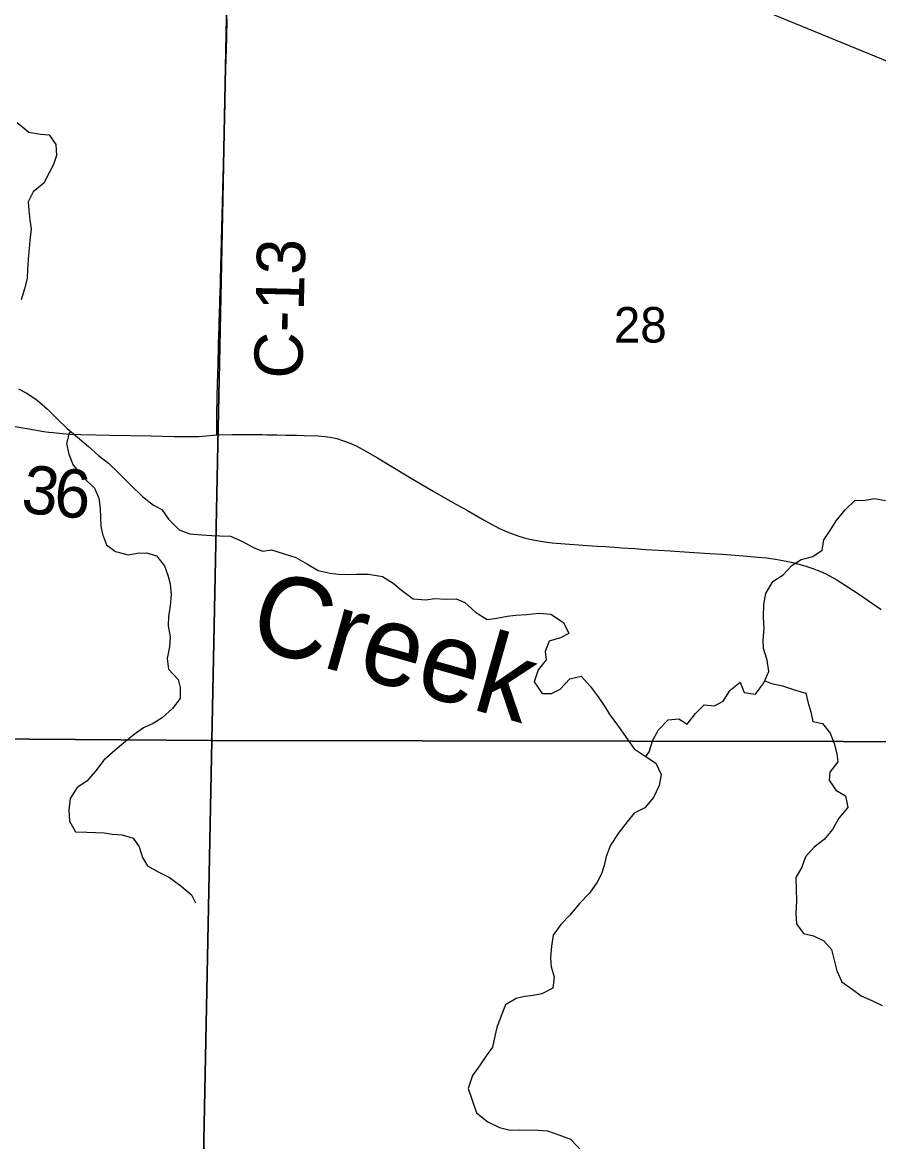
# Model space of a CAD drawing. Extents: x 0 to 34, y 0 to 22.
# Drawn here: x 4.621 to 5.125, y 15.009 to 15.668 of the extents above; entities that cross this region are included whole.
import ezdxf

# ---------------------------------------------------------------- set-up
doc = ezdxf.new("R2010")
doc.units = 0
for name, color, linetype in [('GM_X_Corporation', 7, 'Continuous'), ('GM_X_County_Road', 7, 'Continuous'), ('GM_X_County_Road_Text', 7, 'Continuous'), ('GM_X_Minor_River', 7, 'Continuous'), ('GM_X_Minor_River_Text', 7, 'Continuous'), ('GM_X_Rail_Line', 7, 'Continuous'), ('GM_X_Section_Text', 7, 'Continuous')]:
    doc.layers.add(name, color=color, linetype=linetype)

msp = doc.modelspace()

# ---------------------------------------------------------------- linework, layer by layer
at = {"layer": 'GM_X_Corporation'}
for points in [[(4.74242, 15.74864), (4.73217, 15.24548), (4.22309, 15.24934), (4.22989, 15.74816)], [(5.23921, 15.74697), (5.2282, 15.24475), (4.73217, 15.24548), (4.74242, 15.74864)], [(4.22309, 15.24934), (4.73217, 15.24548), (4.72231, 14.74459), (4.71681, 14.74463), (4.22002, 14.74366), (4.21755, 14.74349)], [(5.2282, 15.24475), (5.21872, 14.74348), (4.72231, 14.74459), (4.73217, 15.24548)]]:
    msp.add_lwpolyline(points, close=True, dxfattribs=at)
at = {"layer": 'GM_X_County_Road'}
for points in [[(4.73516, 15.42552), (4.73514, 15.4363), (4.73526, 15.43986), (4.73539, 15.44526), (4.73539, 15.44743), (4.73544, 15.45085), (4.73549, 15.45302), (4.73555, 15.45551), (4.73591, 15.46762), (4.73616, 15.47663), (4.73621, 15.47911), (4.73651, 15.48905), (4.73665, 15.49308), (4.73675, 15.49618), (4.73723, 15.51109), (4.73729, 15.51264), (4.73736, 15.51512), (4.73743, 15.5173), (4.73779, 15.53221), (4.73814, 15.54774), (4.73852, 15.56232), (4.7387, 15.57039), (4.73913, 15.58436), (4.73975, 15.60611), (4.74006, 15.62042), (4.74017, 15.62787), (4.74038, 15.63563), (4.74085, 15.65241), (4.741, 15.65924), (4.74128, 15.67037)], [(4.59378, 15.43804), (4.59465, 15.43756), (4.59798, 15.436), (4.60205, 15.43423), (4.60554, 15.43304), (4.60892, 15.43209), (4.61414, 15.4309), (4.62442, 15.42905), (4.63334, 15.42758), (4.63618, 15.42716), (4.6389, 15.42684), (4.64424, 15.42634), (4.64889, 15.42602), (4.65505, 15.42573), (4.6722, 15.4254), (4.69659, 15.42492), (4.71003, 15.42459), (4.71673, 15.42447), (4.72163, 15.42451), (4.72455, 15.42464), (4.72685, 15.4248), (4.73516, 15.42552)], [(4.73516, 15.42552), (4.74425, 15.42569), (4.74767, 15.42571), (4.75667, 15.42569), (4.76101, 15.42565), (4.76194, 15.42563), (4.76471, 15.42558), (4.77059, 15.42552), (4.77575, 15.42535), (4.78216, 15.42525), (4.78665, 15.42514), (4.79509, 15.42487), (4.79887, 15.42459), (4.80199, 15.42416), (4.80588, 15.42328), (4.80928, 15.42229), (4.81317, 15.42082), (4.81722, 15.41896), (4.82124, 15.41684), (4.82977, 15.41189), (4.83892, 15.40647), (4.84829, 15.40078), (4.86269, 15.39234), (4.87425, 15.38572), (4.88275, 15.38101), (4.89255, 15.37537), (4.89836, 15.3722), (4.90214, 15.37023), (4.90614, 15.36847), (4.90937, 15.36716), (4.9131, 15.36585), (4.91698, 15.36475), (4.91951, 15.36415), (4.92241, 15.36356), (4.92476, 15.36306), (4.92727, 15.36265), (4.92953, 15.36234), (4.93271, 15.36202), (4.94284, 15.3612), (4.95341, 15.36043), (4.95941, 15.36001), (4.96406, 15.35968), (4.97181, 15.35919), (4.97367, 15.35907), (4.98142, 15.35852), (4.98762, 15.35809), (4.99537, 15.35755), (5.00219, 15.35715), (5.01329, 15.35645), (5.02545, 15.35565), (5.0332, 15.35516), (5.04517, 15.35432), (5.05396, 15.35358), (5.05891, 15.35302), (5.06415, 15.35228), (5.06845, 15.35153), (5.07334, 15.35052), (5.07789, 15.34944), (5.08006, 15.34885), (5.0821, 15.34826), (5.08624, 15.34685), (5.0903, 15.34523), (5.09342, 15.34381), (5.09649, 15.34226), (5.10028, 15.3401), (5.10585, 15.33666), (5.11312, 15.33186), (5.12647, 15.32275)]]:
    msp.add_lwpolyline(points, dxfattribs=at)
at = {"layer": 'GM_X_Minor_River'}
for points in [[(4.61757, 15.60947), (4.62455, 15.60373), (4.63137, 15.60254), (4.63649, 15.60212), (4.64044, 15.59659), (4.64077, 15.59013), (4.63902, 15.58483), (4.63652, 15.57992), (4.63325, 15.57368), (4.62695, 15.56861), (4.62406, 15.56275), (4.62441, 15.55781), (4.62512, 15.55192), (4.62585, 15.5468), (4.62504, 15.53997), (4.62462, 15.53523), (4.62401, 15.52897), (4.62377, 15.52271), (4.62355, 15.51759), (4.62198, 15.51153), (4.62004, 15.50509)], [(4.61833, 15.45255), (4.62325, 15.45005), (4.62948, 15.44601), (4.63551, 15.44066), (4.64116, 15.43492), (4.647, 15.42919), (4.65323, 15.42421), (4.65964, 15.41865), (4.66548, 15.4133), (4.67133, 15.40889), (4.67736, 15.40315), (4.68452, 15.39589), (4.69149, 15.3892), (4.6979, 15.38402), (4.70282, 15.38152), (4.70676, 15.3758), (4.71297, 15.36968), (4.71922, 15.36717), (4.72642, 15.36654), (4.7323, 15.36631)], [(4.64901, 15.42758), (4.64831, 15.42652), (4.64675, 15.42046), (4.64803, 15.41419), (4.65064, 15.40772), (4.65666, 15.40046), (4.66306, 15.39415), (4.66568, 15.38825), (4.66658, 15.38217), (4.66673, 15.37686), (4.66688, 15.37173), (4.6678, 15.36698), (4.67022, 15.3607), (4.6755, 15.35687), (4.68289, 15.35492), (4.68821, 15.35582), (4.69371, 15.35597), (4.69958, 15.35422), (4.70447, 15.3483), (4.70633, 15.34279), (4.70762, 15.33784), (4.70833, 15.33158), (4.70771, 15.32475), (4.70672, 15.3185), (4.70649, 15.313), (4.70777, 15.30654), (4.70735, 15.30066), (4.70597, 15.29384), (4.70669, 15.28757), (4.71233, 15.28145), (4.71363, 15.2767), (4.71358, 15.27025), (4.70917, 15.2644), (4.70306, 15.25895), (4.69773, 15.25557), (4.69201, 15.25296), (4.68648, 15.24901), (4.68019, 15.24394), (4.67503, 15.23961), (4.66873, 15.23397), (4.66375, 15.22737), (4.65858, 15.22152), (4.65286, 15.21777), (4.64883, 15.21135), (4.64802, 15.20452), (4.64836, 15.19807), (4.65191, 15.19178), (4.65855, 15.19154), (4.6688, 15.19109), (4.67353, 15.19029), (4.67941, 15.18987), (4.68585, 15.18792), (4.68942, 15.18296), (4.69146, 15.17669), (4.69446, 15.17173), (4.70069, 15.16808), (4.70731, 15.1648), (4.71392, 15.16001), (4.72033, 15.15465), (4.72257, 15.14989)], [(4.98793, 15.23602), (4.98979, 15.23876), (4.99193, 15.24577), (4.99539, 15.25181), (5.00094, 15.25765), (5.0072, 15.25836), (5.01211, 15.2551), (5.01709, 15.26133), (5.02225, 15.2666), (5.02832, 15.26598), (5.03346, 15.2686), (5.03749, 15.27521), (5.04341, 15.27991), (5.04583, 15.27382), (5.05246, 15.27282), (5.05725, 15.27943), (5.06034, 15.28624), (5.05925, 15.29288), (5.05721, 15.29973), (5.05687, 15.30467), (5.05749, 15.31149), (5.05716, 15.31795), (5.0574, 15.32572), (5.05859, 15.33217), (5.06262, 15.33916), (5.06872, 15.3431), (5.07389, 15.34856), (5.07922, 15.35212), (5.08626, 15.35397), (5.0916, 15.35753), (5.09259, 15.36379), (5.09643, 15.36926), (5.09988, 15.37493), (5.10524, 15.38134), (5.11116, 15.38699), (5.11591, 15.38695), (5.12255, 15.38804), (5.129, 15.38685)], [(4.7323, 15.36631), (4.73705, 15.36608), (4.7433, 15.36585), (4.74992, 15.36295), (4.75673, 15.3591), (4.76202, 15.35698), (4.76734, 15.35789), (4.77435, 15.35556), (4.78173, 15.35322), (4.78853, 15.34938), (4.79496, 15.34572), (4.80196, 15.34415), (4.80689, 15.34355), (4.81239, 15.34332), (4.81752, 15.34347), (4.82454, 15.34341), (4.83269, 15.34202), (4.83911, 15.33818), (4.84401, 15.33397), (4.8508, 15.32899), (4.8582, 15.32836), (4.86352, 15.32908), (4.86997, 15.32884), (4.87623, 15.32898), (4.88134, 15.32686), (4.88756, 15.32112), (4.89436, 15.3167), (4.90005, 15.31761), (4.90613, 15.3187), (4.91107, 15.31924), (4.91753, 15.31976), (4.92493, 15.32046), (4.93195, 15.31984), (4.93931, 15.31504), (4.94249, 15.30856), (4.93754, 15.30594), (4.93088, 15.3041), (4.92856, 15.29785), (4.92909, 15.29311), (4.9245, 15.28707), (4.92217, 15.28007), (4.92686, 15.2732), (4.93236, 15.27316), (4.93732, 15.27578), (4.94305, 15.28181), (4.94971, 15.28346), (4.95498, 15.27754), (4.95967, 15.27124), (4.96305, 15.26629), (4.96699, 15.25999), (4.97131, 15.25427), (4.9762, 15.24721), (4.98089, 15.24054), (4.9875, 15.23631), (4.99373, 15.23209), (4.99691, 15.22543), (4.99572, 15.21898), (4.99244, 15.21199), (4.98728, 15.20595), (4.98099, 15.20278), (4.97678, 15.19769), (4.97161, 15.1907), (4.96701, 15.18391), (4.96449, 15.17729), (4.96331, 15.17198), (4.96176, 15.16706), (4.95926, 15.16215), (4.95466, 15.15554), (4.94873, 15.14951), (4.94299, 15.14273), (4.93783, 15.13707), (4.93323, 15.13085), (4.93223, 15.1244), (4.93161, 15.11777), (4.93214, 15.11226), (4.93381, 15.10637), (4.933, 15.09973), (4.92653, 15.09636), (4.92158, 15.09526), (4.91665, 15.09473), (4.91152, 15.09363), (4.90523, 15.08988), (4.90271, 15.08345), (4.90001, 15.07645), (4.89883, 15.07134), (4.89746, 15.0649), (4.89381, 15.0598), (4.89036, 15.05452), (4.88576, 15.04829), (4.88324, 15.04053), (4.88565, 15.03368), (4.88807, 15.02626), (4.89486, 15.0209), (4.90167, 15.01762), (4.90791, 15.01606), (4.91323, 15.01621), (4.92461, 15.01612), (4.92992, 15.0157), (4.93654, 15.01318), (4.94355, 15.01066), (4.95013, 15.00359)], [(5.05784, 15.28073), (5.06181, 15.27901), (5.06825, 15.27764), (5.07601, 15.27511), (5.08207, 15.27336), (5.08317, 15.26823), (5.08502, 15.26233), (5.08612, 15.25663), (5.0918, 15.25545), (5.09632, 15.24991), (5.09874, 15.24382), (5.1004, 15.23774), (5.10094, 15.23299), (5.09615, 15.22696), (5.09573, 15.22222), (5.09968, 15.21631), (5.10534, 15.21285), (5.10681, 15.206), (5.10145, 15.19978), (5.0978, 15.19317), (5.09282, 15.18714), (5.08691, 15.18263), (5.08193, 15.17697), (5.0798, 15.17092), (5.07615, 15.16487), (5.07629, 15.15785), (5.07662, 15.15102), (5.07619, 15.14362), (5.07652, 15.13755), (5.08066, 15.13182), (5.08653, 15.13045), (5.09258, 15.12756), (5.09709, 15.1224), (5.09876, 15.11613), (5.10023, 15.10986), (5.10322, 15.10338), (5.10926, 15.09897), (5.11473, 15.09514), (5.12097, 15.09243), (5.12702, 15.08954)]]:
    msp.add_lwpolyline(points, dxfattribs=at)
at = {"layer": 'GM_X_Rail_Line'}
msp.add_lwpolyline([(4.96716, 15.7129), (5.05909, 15.67461), (5.1678, 15.63018), (5.39384, 15.54176), (5.52024, 15.49129), (5.83989, 15.36317), (6.13681, 15.243), (6.47574, 15.10782), (6.81225, 14.9725), (7.12712, 14.84643), (7.20118, 14.81633), (7.23762, 14.8006), (7.26101, 14.78909), (7.28069, 14.77741), (7.30485, 14.75929), (7.33505, 14.73642), (7.46353, 14.63063), (7.59863, 14.51378), (7.74545, 14.39197), (7.99553, 14.18171), (8.05229, 14.13528), (8.0918, 14.10075), (8.09257, 14.1)], dxfattribs=at)

# ---------------------------------------------------------------- texts
at = {"layer": 'GM_X_County_Road_Text'}
for s, height, rotation, p in [('C-13', 0.028409, 88.66081, (4.78545, 15.45835)), ('3', 0.02841, 351.96822, (4.61916, 15.38025)), ('6', 0.02841, 356.22109, (4.63878, 15.37756))]:
    msp.add_text(s, height=height, rotation=rotation, dxfattribs=at).set_placement(p)
at = {"layer": 'GM_X_Minor_River_Text'}
msp.add_text('Creek', height=0.047369, rotation=344.22331, dxfattribs=at).set_placement((4.75224, 15.30153))
at = {"layer": 'GM_X_Section_Text'}
msp.add_text('28', height=0.020928, rotation=0.00001, dxfattribs=at).set_placement((4.96902, 15.47988))

doc.saveas('drawing.dxf')
